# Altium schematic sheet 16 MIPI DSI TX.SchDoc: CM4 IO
size 420 x 297 mm; Page Create Date: March  8, 1995; Page Number: 16; Page Size: A3; Comment: radxa_1010; Page Count: 19; RevCode: V1.10; Doc: 16 MIPI DSI TX; DsnPath: D:\WMS\黄工\[RC126]CM4_IO_V1.10\[RC126]_V1.10\CM4 IO_V1.10.DSN; SchematicName: CM4 IO V1.10; PageName: 16 MIPI DSI TX; PageSize: A3; TopSchematic: True
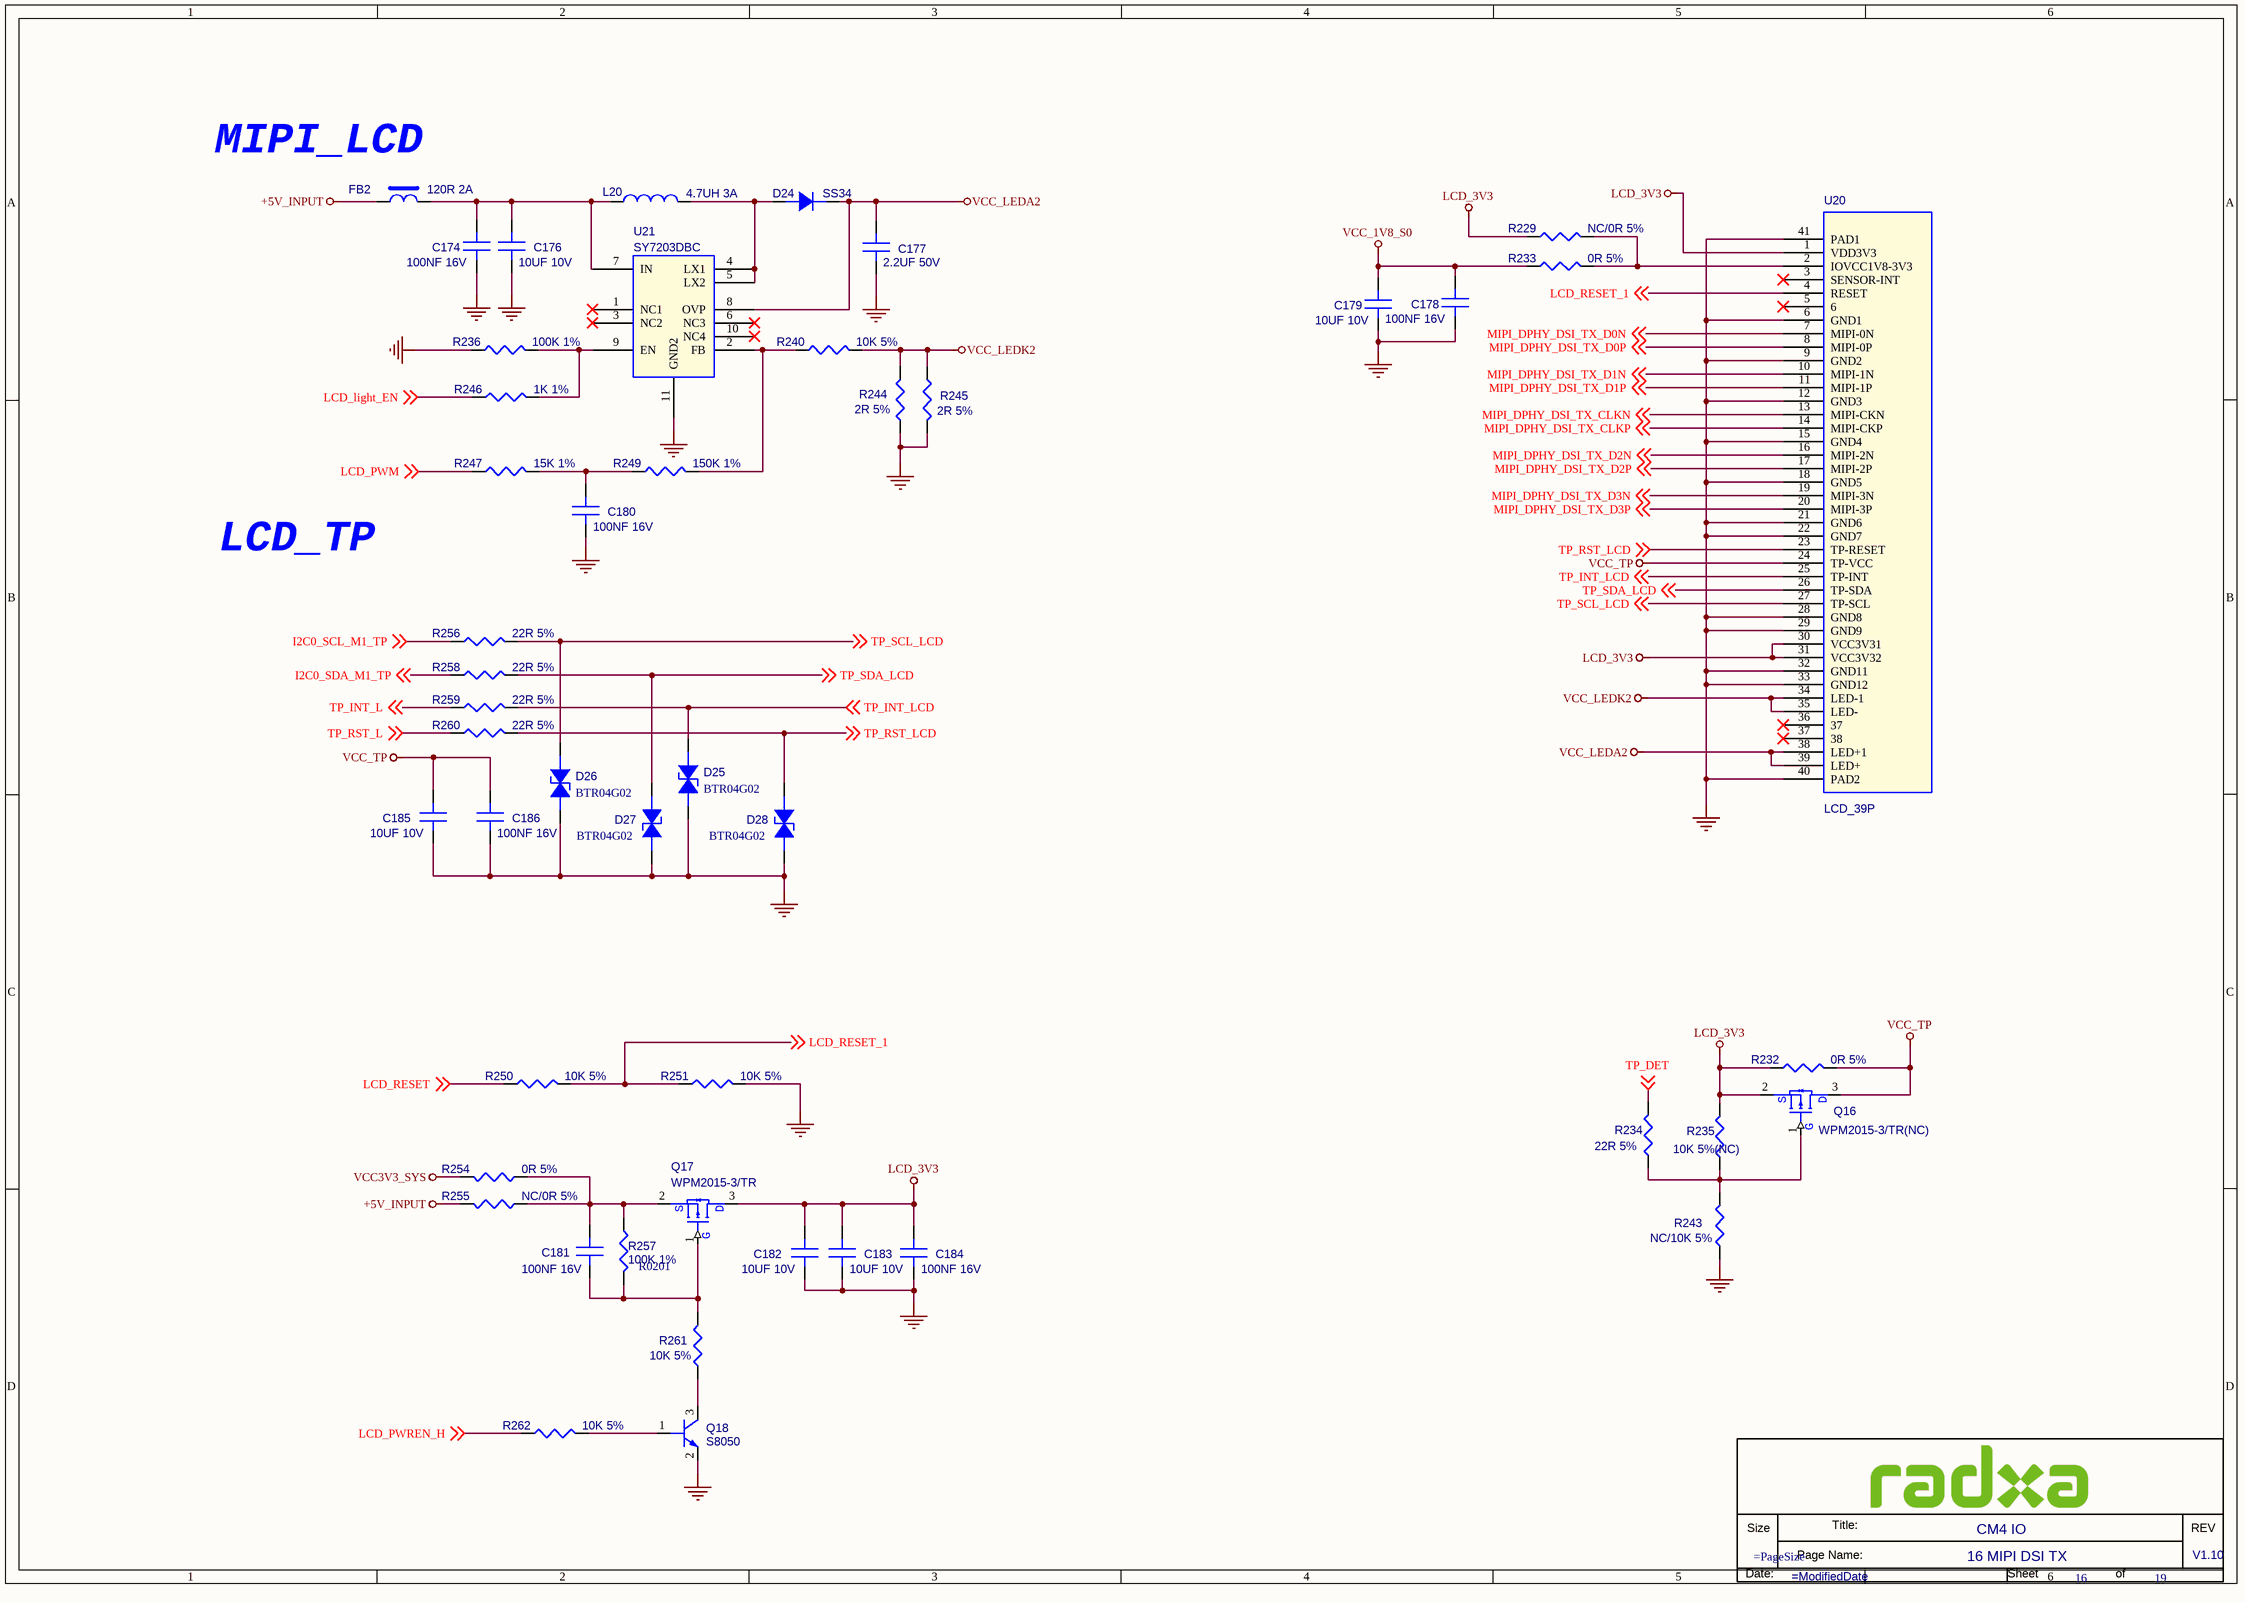
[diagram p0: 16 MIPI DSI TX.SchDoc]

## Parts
*  Doc: 16 MIPI DSI TX  RevCode: V1.10  Title: CM4 IO  Page Number: 16  Page Count: 19  (hidden comment: radxa_1010)  (graphical)
C174  100NF 16V  [C0201]
C176  10UF 10V  [C0603]
C177  2.2UF 50V  [C0603]
C178  100NF 16V  [C0201]
C179  10UF 10V  [C0603]
C180  100NF 16V  [C0201]
C181  100NF 16V  [C0201]
C182  10UF 10V  [C0603]
C183  10UF 10V  [C0603]
C184  100NF 16V  [C0201]
C185  10UF 10V  [C0603]
C186  100NF 16V  [C0201]
D24  SS34  [DO_214AC]
D25  BTR04G02  [DFN1006-2L]
D26  BTR04G02  [DFN1006-2L]
D27  BTR04G02  [DFN1006-2L]
D28  BTR04G02  [DFN1006-2L]
FB2  120R 2A  [FB0603]
L20  4.7UH 3A  [L_3015]
Q16  WPM2015-3/TR(NC)  [SOT_23]
Q17  WPM2015-3/TR  [SOT_23]
Q18  S8050  [SOT_23]
R229  NC/0R 5%  [R0402]
R232  0R 5%  [R0402]
R233  0R 5%  [R0402]
R234  22R 5%  [R0402]
R235  10K 5%(NC)  [R0402]
R236  100K 1%  [R0402]
R240  10K 5%  [R0402]
R243  NC/10K 5%  [R0402]
R244  2R 5%  [R0402]
R245  2R 5%  [R0402]
R246  1K 1%  [R0402]
R247  15K 1%  [R0402]
R249  150K 1%  [R0402]
R250  10K 5%  [R0402]
R251  10K 5%  [R0402]
R254  0R 5%  [R0402]
R255  NC/0R 5%  [R0402]
R256  22R 5%  [R0402]
R257  100K 1%  PCB Footprint: R0201  [R0402]
R258  22R 5%  [R0402]
R259  22R 5%  [R0402]
R260  22R 5%  [R0402]
R261  10K 5%  [R0402]
R262  10K 5%  [R0402]
U20  LCD_39P  [FPC_39P_0D3_LIE]
U21  SY7203DBC  [DFN10_0D5_3]

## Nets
+5V_INPUT: FB2.1 R255.1
GND: C174.2(B) C176.2(B) C177.2(B) C178.2(B) C179.2(B) C180.1(A) C182.2(B) C183.2(B) C184.2(B) C185.2(B) C186.2(B) D25.2(CATHODE) D26.2(CATHODE) D27.2(CATHODE) D28.2(CATHODE) Q18.2(EMITTER) R236.1 R243.1 R244.2 R245.2 R251.2 U20.6(GND1) U20.9(GND2) U20.12(GND3) U20.15(GND4) U20.18(GND5) U20.21(GND6) U20.22(GND7) U20.28(GND8) U20.29(GND9) U20.32(GND11) U20.33(GND12) U20.40(PAD2) U20.41(PAD1) U21.11(GND2)
LCD_3V3: C182.1(A) C183.1(A) C184.1(A) Q16.2(S) Q17.3(D) R229.1 R232.1 R235.2 U20.1(VDD3V3) U20.30(VCC3V31) U20.31(VCC3V32)
VCC3V3_SYS: R254.1
VCC_1V8_S0: C178.1(A) C179.1(A) R233.1
VCC_LEDA2: C177.1(A) D24.2(K) U20.38(LED+1) U20.39(LED+) U21.8(OVP)
VCC_LEDK2: R240.2 R244.1 R245.1 U20.34(LED-1) U20.35(LED-)
VCC_TP: C185.1(A) C186.1(A) Q16.3(D) R232.2 U20.24(TP-VCC)
I2C0_SCL_M1_TP: R256.1 ; off-sheet I2C0_SCL_M1_TP
I2C0_SDA_M1_TP: R258.1 ; off-sheet I2C0_SDA_M1_TP
LCD_light_EN: R246.1 ; off-sheet LCD_light_EN
LCD_PWM: R247.1 ; off-sheet LCD_PWM
LCD_PWREN_H: R262.1 ; off-sheet LCD_PWREN_H
LCD_RESET: R250.1 ; off-sheet LCD_RESET
LCD_RESET_1: R250.2 R251.1 U20.4(RESET) ; off-sheet LCD_RESET_1
MIPI_DPHY_DSI_TX_CLKN: U20.13(MIPI-CKN) ; off-sheet MIPI_DPHY_DSI_TX_CLKN
MIPI_DPHY_DSI_TX_CLKP: U20.14(MIPI-CKP) ; off-sheet MIPI_DPHY_DSI_TX_CLKP
MIPI_DPHY_DSI_TX_D0N: U20.7(MIPI-0N) ; off-sheet MIPI_DPHY_DSI_TX_D0N
MIPI_DPHY_DSI_TX_D0P: U20.8(MIPI-0P) ; off-sheet MIPI_DPHY_DSI_TX_D0P
MIPI_DPHY_DSI_TX_D1N: U20.10(MIPI-1N) ; off-sheet MIPI_DPHY_DSI_TX_D1N
MIPI_DPHY_DSI_TX_D1P: U20.11(MIPI-1P) ; off-sheet MIPI_DPHY_DSI_TX_D1P
MIPI_DPHY_DSI_TX_D2N: U20.16(MIPI-2N) ; off-sheet MIPI_DPHY_DSI_TX_D2N
MIPI_DPHY_DSI_TX_D2P: U20.17(MIPI-2P) ; off-sheet MIPI_DPHY_DSI_TX_D2P
MIPI_DPHY_DSI_TX_D3N: U20.19(MIPI-3N) ; off-sheet MIPI_DPHY_DSI_TX_D3N
MIPI_DPHY_DSI_TX_D3P: U20.20(MIPI-3P) ; off-sheet MIPI_DPHY_DSI_TX_D3P
TP_DET: R234.1 ; off-sheet TP_DET
TP_INT_L: R259.1 ; off-sheet TP_INT_L
TP_INT_LCD: D25.1(ANODE) R259.2 U20.25(TP-INT) ; off-sheet TP_INT_LCD
TP_RST_L: R260.1 ; off-sheet TP_RST_L
TP_RST_LCD: D28.1(ANODE) R260.2 U20.23(TP-RESET) ; off-sheet TP_RST_LCD
TP_SCL_LCD: D26.1(ANODE) R256.2 U20.27(TP-SCL) ; off-sheet TP_SCL_LCD
TP_SDA_LCD: D27.1(ANODE) R258.2 U20.26(TP-SDA) ; off-sheet TP_SDA_LCD
NetC174_1: C174.1(A) C176.1(A) FB2.2 L20.1 U21.7(IN)
NetC180_2: C180.2(B) R247.2 R249.1
NetC181_1: C181.1(A) Q17.2(S) R254.2 R255.2 R257.1
NetC181_2: C181.2(B) Q17.1(G) R257.2 R261.1
NetD24_1: D24.1(A) L20.2 U21.4(LX1) U21.5(LX2)
NetQ16_1: Q16.1(G) R234.2 R235.1 R243.2
NetQ18_1: Q18.1(BASE) R262.2
NetQ18_3: Q18.3(COLLECTOR) R261.2
NetR229_2: R229.2 R233.2 U20.2(IOVCC1V8-3V3)
NetR236_2: R236.2 R246.2 U21.9(EN)
NetR240_1: R240.1 R249.2 U21.2(FB)

Not connected (* = marked no-connect by the designer): U20 3(SENSOR-INT)* 5(6)* 36(37)* 37(38)*; U21 1(NC1)* 3(NC2)* 6(NC3)* 10(NC4)*

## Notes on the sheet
- (near FB2) MIPI_LCD
- LCD_TP

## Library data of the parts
C174 = C: SMD  0201  100NF  16V  X5R  ±20%  ROHS; PARTS: 1; Part Reference: C174; Part Number: A1C01.00099; OriginalSymbolOrigin: (0,30); PKG_TYPE: CAP2-100-250; LEVEL: STD; PINSWAP: (A,B); Preferred: 6715f349cd0bc5
C176 = C: SMD  0603  10UF  10V  X5R  ±10%  ROHS; PARTS: 1; Part Reference: C176; Part Number: A1C01.00270; OriginalSymbolOrigin: (0,30); PKG_TYPE: CAP2-100-250; LEVEL: STD; PINSWAP: (A,B)
C177 = C: SMD  0603  2.2UF  50V  X5R  ±10%  ROHS; PARTS: 1; Part Reference: C177; Part Number: A1C01.00235; OriginalSymbolOrigin: (0,30); PKG_TYPE: CAP2-100-250; LEVEL: STD; PINSWAP: (A,B)
C178 = C: SMD  0201  100NF  16V  X5R  ±20%  ROHS; PARTS: 1; Part Reference: C178; Part Number: A1C01.00099; OriginalSymbolOrigin: (0,30); PKG_TYPE: CAP2-100-250; LEVEL: STD; PINSWAP: (A,B); Preferred: 6715f349cd0bc5
C179 = C: SMD  0603  10UF  10V  X5R  ±10%  ROHS; PARTS: 1; Part Reference: C179; Part Number: A1C01.00270; OriginalSymbolOrigin: (0,30); PKG_TYPE: CAP2-100-250; LEVEL: STD; PINSWAP: (A,B)
C180 = C: SMD  0201  100NF  16V  X5R  ±20%  ROHS; PARTS: 1; Part Reference: C180; Part Number: A1C01.00099; OriginalSymbolOrigin: (0,30); PKG_TYPE: CAP2-100-250; LEVEL: STD; PINSWAP: (A,B); Preferred: 6715f349cd0bc5
C181 = C: SMD  0201  100NF  16V  X5R  ±20%  ROHS; PARTS: 1; Part Reference: C181; Part Number: A1C01.00099; OriginalSymbolOrigin: (0,30); PKG_TYPE: CAP2-100-250; LEVEL: STD; PINSWAP: (A,B); Preferred: 6715f349cd0bc5
C182 = C: SMD  0603  10UF  10V  X5R  ±10%  ROHS; PARTS: 1; Part Reference: C182; Part Number: A1C01.00270; OriginalSymbolOrigin: (0,30); PKG_TYPE: CAP2-100-250; LEVEL: STD; PINSWAP: (A,B)
C183 = C: SMD  0603  10UF  10V  X5R  ±10%  ROHS; PARTS: 1; Part Reference: C183; Part Number: A1C01.00270; OriginalSymbolOrigin: (0,30); PKG_TYPE: CAP2-100-250; LEVEL: STD; PINSWAP: (A,B)
C184 = C: SMD  0201  100NF  16V  X5R  ±20%  ROHS; PARTS: 1; Part Reference: C184; Part Number: A1C01.00099; OriginalSymbolOrigin: (0,30); PKG_TYPE: CAP2-100-250; LEVEL: STD; PINSWAP: (A,B); Preferred: 6715f349cd0bc5
C185 = C: SMD  0603  10UF  10V  X5R  ±10%  ROHS; PARTS: 1; Part Reference: C185; Part Number: A1C01.00270; OriginalSymbolOrigin: (0,30); PKG_TYPE: CAP2-100-250; LEVEL: STD; PINSWAP: (A,B)
C186 = C: SMD  0201  100NF  16V  X5R  ±20%  ROHS; PARTS: 1; Part Reference: C186; Part Number: A1C01.00099; OriginalSymbolOrigin: (0,30); PKG_TYPE: CAP2-100-250; LEVEL: STD; PINSWAP: (A,B); Preferred: 6715f349cd0bc5
D24 = DIODE: SMD  编带  DO-214AC  SS34  CJ  ROHS; Part Reference: D24; Part Number: A1D02.00052
D25 = ESD: SMD  编带  0402  BTR04G02  B-tron  ROHS; Part Reference: D25; Part Number: A1D02.00002; Parameter: ESD-台舟 ESD5341N-封装 esd0402; ID: DE-E0004; PCB Footprint: ESD_D0402; Temp Coeff: -50℃ ~ +125℃
D26 = ESD: SMD  编带  0402  BTR04G02  B-tron  ROHS; Part Reference: D26; Part Number: A1D02.00002; Parameter: ESD-台舟 ESD5341N-封装 esd0402; ID: DE-E0004; PCB Footprint: ESD_D0402; Temp Coeff: -50℃ ~ +125℃
D27 = ESD: SMD  编带  0402  BTR04G02  B-tron  ROHS; Part Reference: D27; Part Number: A1D02.00002; Parameter: ESD-台舟 ESD5341N-封装 esd0402; ID: DE-E0004; PCB Footprint: ESD_D0402; Temp Coeff: -50℃ ~ +125℃
D28 = ESD: SMD  编带  0402  BTR04G02  B-tron  ROHS; Part Reference: D28; Part Number: A1D02.00002; Parameter: ESD-台舟 ESD5341N-封装 esd0402; ID: DE-E0004; PCB Footprint: ESD_D0402; Temp Coeff: -50℃ ~ +125℃
FB2 = BEAD: SMD  0603  FB120R  2A  PZ1608U121-2R0TF  ±25%  Sunlord(顺络)  ROHS; Part Reference: FB2; Part Number: A1L09.00003; Temp Coeff: -55℃~+125℃
L20 = L: SMD  带屏蔽  3*3*1.5mm  4.7UH  3A  ±20%  RXWHJ3015-4R7MT  ROHS; Part Reference: L20; Part Number: A1L01.00021
Q16 = MOSFET_PNP: SMD编带  SOT-23  WPM2015-3/TR  P沟道  ROHS; Part Reference: Q16; Part Number: A1D01.00019; Temp Coeff: -55℃ to ＋150℃
Q17 = MOSFET_PNP: SMD编带  SOT-23  WPM2015-3/TR  P沟道  ROHS; Part Reference: Q17; Part Number: A1D01.00019; Temp Coeff: -55℃ to ＋150℃
Q18 = NPN: SMD编带  SOT-23  S8050  NPN  ROHS; Part Reference: Q18; Part Number: A1D01.00009; Manufacturer PN: S8050_SOT23; Manufacturer: 长电; Temp Coeff: -55℃ to ＋150℃; Pc: 0.3W; Vceo: 25V; Ic: 0.5A; Priority: A
R229 = R: SMD  0201  0R  1/20W  ±5%  ROHS; Part Reference: R229; Part Number: A1R01.00027; PCB Footprint: R0201; Temp Coeff: －55℃ ~ ＋125℃
R232 = R: SMD  0201  0R  1/20W  ±5%  ROHS; Part Reference: R232; Part Number: A1R01.00027; PCB Footprint: R0201; Temp Coeff: －55℃ ~ ＋125℃
R233 = R: SMD  0201  0R  1/20W  ±5%  ROHS; Part Reference: R233; Part Number: A1R01.00027; PCB Footprint: R0201; Temp Coeff: －55℃ ~ ＋125℃
R234 = R: SMD  0201  22R  1/20W  ±5%  ROHS; Part Reference: R234; Part Number: A1R01.00024; PCB Footprint: R0201
R235 = R: SMD  0201  10K  1/20W  ±5%  ROHS; Part Reference: R235; Part Number: A1R01.00012; PCB Footprint: R0201; Temp Coeff: －55℃ ~ ＋125℃
R236 = R: SMD  0201  100K  1/20W  ±1%  ROHS; Part Reference: R236; Part Number: A1R01.00165; Preferred: 6715f349cd0bc5
R240 = R: SMD  0201  10K  1/20W  ±5%  ROHS; Part Reference: R240; Part Number: A1R01.00012; PCB Footprint: R0201; Temp Coeff: －55℃ ~ ＋125℃
R243 = R: SMD  0201  10K  1/20W  ±5%  ROHS; Part Reference: R243; Part Number: A1R01.00012; PCB Footprint: R0201; Temp Coeff: －55℃ ~ ＋125℃
R244 = R: SMD  0603  2R  1/10W  ±5%  ROHS; Part Reference: R244; Part Number: A1R01.00329; PCB Footprint: R0603
R245 = R: SMD  0603  2R  1/10W  ±5%  ROHS; Part Reference: R245; Part Number: A1R01.00329; PCB Footprint: R0603
R246 = R: SMD  0201  1K  1/20W  ±1%  ROHS; Part Reference: R246; Part Number: A1R01.00111; PCB Footprint: R0201
R247 = R: SMD  0201  15K  1/20W  ±1%  ROHS; Part Reference: R247; Part Number: A1R01.00119; PCB Footprint: R0201
R249 = R: SMD  0201  150K  1/20W  ±1%  ROHS; Part Reference: R249; Part Number: A1R01.00095; PCB Footprint: R0201
R250 = R: SMD  0201  10K  1/20W  ±5%  ROHS; Part Reference: R250; Part Number: A1R01.00012; PCB Footprint: R0201; Temp Coeff: －55℃ ~ ＋125℃
R251 = R: SMD  0201  10K  1/20W  ±5%  ROHS; Part Reference: R251; Part Number: A1R01.00012; PCB Footprint: R0201; Temp Coeff: －55℃ ~ ＋125℃
R254 = R: SMD  0402  0R  1/16W  ±5%  ROHS; Part Reference: R254; Part Number: A1R01.00030
R255 = R: SMD  0201  0R  1/20W  ±5%  ROHS; Part Reference: R255; Part Number: A1R01.00027; PCB Footprint: R0201; Temp Coeff: －55℃ ~ ＋125℃
R256 = R: SMD  0201  22R  1/20W  ±5%  ROHS; Part Reference: R256; Part Number: A1R01.00024; PCB Footprint: R0201
R257 = R: SMD  0201  100K  1/20W  ±1%  ROHS; Part Reference: R257; Part Number: A1R01.00165; Preferred: 6715f349cd0bc5
R258 = R: SMD  0201  22R  1/20W  ±5%  ROHS; Part Reference: R258; Part Number: A1R01.00024; PCB Footprint: R0201
R259 = R: SMD  0201  22R  1/20W  ±5%  ROHS; Part Reference: R259; Part Number: A1R01.00024; PCB Footprint: R0201
R260 = R: SMD  0201  22R  1/20W  ±5%  ROHS; Part Reference: R260; Part Number: A1R01.00024; PCB Footprint: R0201
R261 = R: SMD  0201  10K  1/20W  ±5%  ROHS; Part Reference: R261; Part Number: A1R01.00012; PCB Footprint: R0201; Temp Coeff: －55℃ ~ ＋125℃
R262 = R: SMD  0201  10K  1/20W  ±5%  ROHS; Part Reference: R262; Part Number: A1R01.00012; PCB Footprint: R0201; Temp Coeff: －55℃ ~ ＋125℃
U20 = LCD_39P: SMD  下接触  卧式  39PIN  0.3mm脚距  后翻盖H1.0  FH35C-39S-0.3SHW(50)  镀金  广濑  ROHS; Part Reference: U20; Part Number: A1J06.00001
U21 = SY7203DBC: SMD  升压  SY7203DBC  DFN3X3-10  silergy(矽力杰)  ROHS; Part Reference: U21; Part Number: A1I01.00260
